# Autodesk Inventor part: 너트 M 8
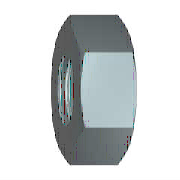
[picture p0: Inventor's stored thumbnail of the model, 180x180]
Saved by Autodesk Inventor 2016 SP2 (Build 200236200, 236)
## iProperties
IsCustomPart: 1
Created: 2012-02
Part Number: 너트 M 8
Material: 강철, 연강
Description: 6각 너트 및 6각 가는 너트
Document SubType Name: Modeling
Standard: KS B 1012
Designer: mduedu
Standards Organization: KS
Language: ko-KR
Size Designation: M 8
Categories: <MemberInstance><Categories><Category DisplayName="조임쇠" InternalName="e4da775c-781d-43d5-af7c-5136215cf5a6" Mnemonic="FSTN"><Category DisplayName="너트" InternalN
Density: 1 g/cm^3
Appearance: 강철
Author: mduedu
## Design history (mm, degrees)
sketch "스케치1"
  geometry: L1 (-7.506, 0)-(-3.753, 6.5); L2 (-3.753, 6.5)-(3.753, 6.5); L3 (3.753, 6.5)-(7.506, 0); L4 (7.506, 0)-(3.753, -6.5); L5 (3.753, -6.5)-(-3.753, -6.5); L6 (-3.753, -6.5)-(-7.506, 0); 2 further points
  constraints: 12 end point, 1 coincident, 1 horizontal, 11 other
  dimensions: "d0" = 15.01111 distance of L3.end L1.start (= 1.1547 x SW)
extrude "본체" new body sketch "스케치1" distance "d1" = 5 (= KOH); taper "d2" = 0 deg
sketch "스케치2"
  geometry: L1 (0, 3.753)-(0, 7.506) reference; L2 (0, 7.506)-(5, 7.506) reference; L3 (5, 3.753)-(5, 7.506) reference; L4 (-1, 0)-(6, 0) reference; L5 (0.581, 7.506)-(0, 6.5); L6 (4.419, 7.506)-(5, 6.5)
  constraints: 4 end point, 4 point on line
  dimensions: "d3" = 30 deg angle of L1 L5 (= ANG1); "d4" = 30 deg angle of L3 L6 (= ANG2); "d5" = 13 diameter of L5.end L4 (= SW0); "d6" = 13 diameter of L6.end L4 (= SW01)
revolve "모따기1" sketch "스케치2" stored, may be unused: angle "d7" = 90 deg
sketch "스케치3"
  geometry: A1 r 6.5 centre (0, 0) between (-3.25, -5.629) and (3.25, -5.629) reference; 1 further point
  constraints: 1 coincident
hole "스레드" sketch "스케치3" at (0, 0) diameter "d25" = 6.647; stored, may be unused: countersink angle "d29" = 82 deg, drill point angle "d31" = 118 deg; dims "d26" = 6, "d27" = 4, "d28" = 2, "d30" = 8
workaxis "Work Axis1"
workplane "Work Plane1"
body "Solid1"
chamfer "모따기2" distance "d8" = 0.67658 (= -0.5 x GD1 + 0.5 x NND); stored, may be unused: angle "d9" = 30 deg, second distance "d40" = 0.67658 (= -0.5 x GD1 + 0.5 x NND)
chamfer "모따기3" distance "d10" = 0.67658 (= -0.5 x GD1 + 0.5 x NND); stored, may be unused: angle "d11" = 30 deg, second distance "d41" = 0.67658 (= -0.5 x GD1 + 0.5 x NND)
other parameters: "ANG1" = 30 deg [user parameter; used in 1 equation term], "ANG2" = 30 deg [user parameter; used in 1 equation term], "NND" = 8 [user parameter; used in 4 equation terms], "KOH" = 5 [user parameter; used in 1 equation term], "SW" = 13 [user parameter; used in 4 equation terms], "SW0" = 13 (= SW) [user parameter; used in 1 equation term], "SW01" = 13 (= SW) [user parameter; used in 1 equation term], "GD1" = 6.64684 (computed from THREADDIA, PTC, TOA) [user parameter; used in 4 equation terms], "d13" = 0, "d14" = 0, "d39" = 0, "d42" = 0, "GUL" = 0.67658 (= 0.541266 x PTC) [user parameter], "TPU" = 8 (computed from PTC) [user parameter], "THREADDIA" = 8 [user parameter; used in 1 equation term], "TOA" = 30 deg [user parameter; used in 1 equation term], "PTC" = 1.25 [user parameter; used in 4 equation terms], "E0" = 15.015 (= 1.155 x SW) [user parameter], "GAL" = 0.67658 (= 0.541266 x PTC) [user parameter]
